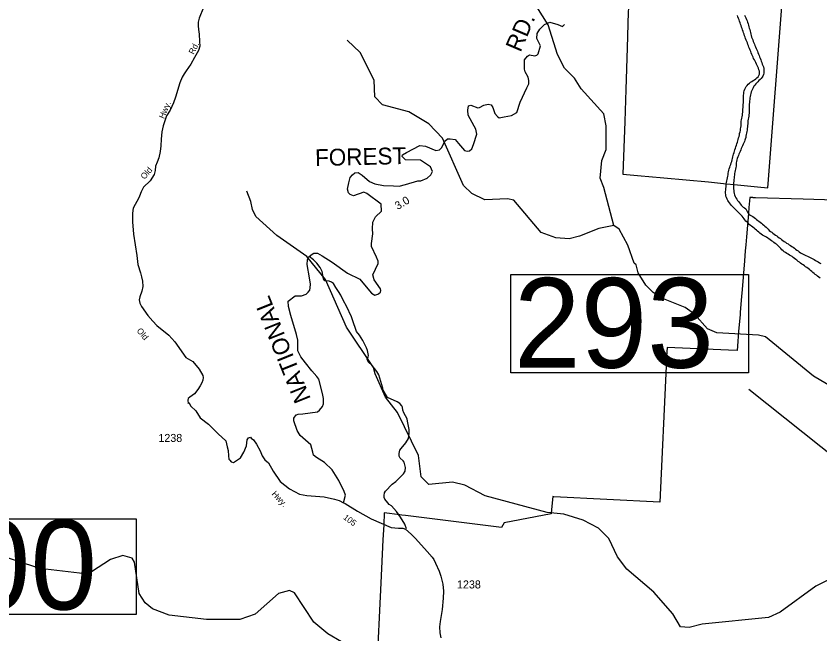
# Model space of a CAD drawing. Extents: x 1113032 to 1302912, y 664689 to 832535.
# Drawn here: x 1126972 to 1139525, y 756257 to 765901 of the extents above; entities that cross this region are included whole.
import ezdxf

# ---------------------------------------------------------------- set-up
doc = ezdxf.new("R2010")
doc.units = 0
for name, color, linetype in [('Exist Boundary Land Use Forest National US Forest Service', 7, 'Continuous'), ('Exist Hydrographic Creek Single Shore', 7, 'Continuous'), ('Exist Hydrographic River Shore', 7, 'Continuous'), ('Exist Road Non-System Type 51', 7, 'Continuous'), ('Exist Road Primary NC Structure Pipe Number Label', 7, 'Continuous'), ('Exist Road Secondary Structure Standard Bridge Number Label', 7, 'Continuous'), ('Exist Road Secondary Type 41 Attributed', 7, 'Continuous'), ('Exist Road Secondary Type 51 Label', 7, 'Continuous'), ('Exist Road Secondary Type 51 Number Label', 7, 'Continuous'), ('Exist Road State Agency Type 20 National Forest', 7, 'Continuous'), ('Exist Road State Agency Type 41 Label', 7, 'Continuous'), ('Exist Road State Agency Type 41 Mileage Label', 7, 'Continuous')]:
    doc.layers.add(name, color=color, linetype=linetype)

msp = doc.modelspace()

# ---------------------------------------------------------------- linework, layer by layer
at = {"layer": 'Exist Boundary Land Use Forest National US Forest Service'}
for points in [[(1138713, 763223), (1138723, 763348), (1138943, 766193), (1138993, 766844), (1139021, 767208), (1138394, 767267), (1138077, 767670), (1137491, 768414), (1137470, 768440), (1137238, 768439), (1137082, 768438), (1137008, 768296), (1137011, 768288), (1136972, 768151), (1137018, 768103), (1137101, 768007), (1137113, 767991), (1137220, 767682), (1136825, 767454), (1136525, 767475), (1136621, 766751), (1136539, 766137)], [(1136539, 766137), (1136539, 766090), (1136530, 765960), (1136513, 765408), (1136497, 764754), (1136478, 764256), (1136446, 763434), (1136733, 763409), (1136853, 763399), (1137087, 763379), (1137787, 763312), (1138068, 763285), (1138186, 763274), (1138552, 763238), (1138713, 763223)], [(1138479, 763072), (1138432, 763072), (1138415, 762916), (1138408, 762820), (1138378, 762456), (1138368, 762329), (1138360, 762238), (1138347, 762083), (1138310, 761636), (1138301, 761526), (1138281, 761280), (1138278, 761242), (1138256, 760980), (1138237, 760749), (1138232, 760682), (1138099, 760687), (1137138, 760728), (1137132, 760594), (1137125, 760438), (1137024, 758315), (1135368, 758399), (1135352, 758400), (1135336, 758200), (1135331, 758131), (1134593, 757989), (1134555, 757920), (1133052, 758105), (1132995, 758112), (1132963, 758116), (1132722, 758146), (1132713, 757960), (1132702, 757727), (1132681, 757278), (1132670, 757055), (1132603, 755652)], [(1138479, 763072), (1138521, 763071), (1139266, 763048), (1140594, 763008), (1141070, 762998), (1142683, 762964), (1142926, 762959), (1142906, 762157), (1143300, 762142)]]:
    msp.add_lwpolyline(points, dxfattribs=at)
at = {"layer": 'Exist Hydrographic Creek Single Shore'}
for points in [[(1136308, 762631), (1136150, 763228), (1136096, 763371), (1136121, 763646), (1136185, 763818), (1136187, 764186), (1136151, 764377), (1135796, 764765), (1135692, 764934), (1135538, 765088), (1135428, 765301), (1135283, 765763), (1135044, 766145), (1134305, 766800)], [(1136308, 762631), (1136073, 762586), (1135769, 762465), (1135610, 762425), (1135402, 762442), (1135171, 762522), (1134744, 763027), (1134644, 763048), (1134294, 763032), (1134088, 763132), (1133958, 763259), (1133630, 763994), (1133420, 764218), (1133108, 764408), (1132695, 764515), (1132573, 764642), (1132564, 764902), (1132344, 765333), (1132141, 765524)], [(1139834, 757190), (1139461, 757001), (1138907, 756599), (1138721, 756514), (1137684, 756410), (1137483, 756358), (1137350, 756370), (1137230, 756573), (1136931, 756907), (1136508, 757270), (1136363, 757460), (1136231, 757745), (1136069, 757909), (1135830, 758032), (1135525, 758127), (1135266, 758152), (1134298, 758411), (1133978, 758581), (1133788, 758628), (1133420, 758589), (1133298, 758710), (1133258, 759042), (1132928, 759712), (1132743, 759952), (1132579, 760316), (1132556, 760415), (1132133, 761044), (1131805, 761789), (1131515, 762146), (1131042, 762477), (1130717, 762772), (1130662, 762882), (1130640, 763007), (1130578, 763166)], [(1139719, 760111), (1139424, 760278), (1138675, 760893), (1138567, 760922), (1137918, 760958), (1137770, 761020), (1137568, 761250), (1137421, 761355), (1137083, 761490), (1136919, 761588), (1136806, 761699), (1136686, 761895), (1136657, 762020), (1136624, 762047), (1136524, 762325), (1136390, 762577), (1136308, 762631)], [(1132055, 756135), (1131841, 756257), (1131622, 756439), (1131318, 756898), (1131244, 756936), (1131068, 756890), (1130708, 756566), (1130464, 756482), (1129947, 756482), (1129365, 756550), (1129101, 756647), (1128987, 756744), (1128892, 756887), (1128823, 757375), (1128783, 757441), (1128642, 757480), (1128449, 757418), (1128151, 757227), (1128050, 757196), (1127344, 757276), (1126625, 757514)]]:
    msp.add_lwpolyline(points, dxfattribs=at)
at = {"layer": 'Exist Hydrographic River Shore'}
for points in [[(1138502, 765217), (1138490, 765238), (1138481, 765260), (1138472, 765282), (1138463, 765304), (1138454, 765327), (1138445, 765349), (1138436, 765371), (1138426, 765393), (1138417, 765415), (1138408, 765437), (1138399, 765460), (1138392, 765482), (1138383, 765505), (1138373, 765527), (1138364, 765549), (1138356, 765571), (1138348, 765594), (1138340, 765617), (1138332, 765639), (1138325, 765662), (1138317, 765685), (1138310, 765708), (1138302, 765731), (1138294, 765753), (1138286, 765776), (1138278, 765798), (1138270, 765821), (1138262, 765844), (1138253, 765866), (1138246, 765889), (1138240, 765912)], [(1138349, 765916), (1138359, 765894), (1138369, 765872), (1138378, 765850), (1138387, 765828), (1138395, 765805), (1138403, 765782), (1138410, 765759), (1138416, 765736), (1138423, 765713), (1138431, 765691), (1138437, 765667), (1138440, 765644), (1138444, 765620), (1138450, 765597), (1138458, 765574), (1138466, 765551), (1138476, 765529), (1138485, 765507)], [(1138485, 765507), (1138493, 765485), (1138502, 765462), (1138511, 765440), (1138519, 765419), (1138530, 765398), (1138540, 765376), (1138550, 765354), (1138558, 765332), (1138566, 765309), (1138575, 765287), (1138583, 765264), (1138592, 765242), (1138601, 765220), (1138609, 765197), (1138618, 765175), (1138626, 765152), (1138635, 765130), (1138643, 765107), (1138648, 765084), (1138650, 765060), (1138652, 765036), (1138650, 765012), (1138644, 764989), (1138635, 764966), (1138622, 764946), (1138607, 764928), (1138590, 764911), (1138572, 764894), (1138555, 764877), (1138539, 764859), (1138523, 764842), (1138507, 764824), (1138491, 764806), (1138481, 764784), (1138471, 764762), (1138460, 764741), (1138454, 764718), (1138448, 764695), (1138443, 764671), (1138437, 764648), (1138433, 764624), (1138429, 764600), (1138426, 764577), (1138424, 764553), (1138422, 764529), (1138421, 764505), (1138422, 764481), (1138422, 764457), (1138422, 764433), (1138423, 764409), (1138421, 764385), (1138417, 764361), (1138413, 764338), (1138409, 764314), (1138405, 764290), (1138402, 764266), (1138399, 764243), (1138398, 764219), (1138395, 764195), (1138393, 764171), (1138391, 764147), (1138388, 764123), (1138384, 764100), (1138380, 764076), (1138376, 764052), (1138371, 764029), (1138366, 764005), (1138359, 763982), (1138354, 763964), (1138347, 763944), (1138338, 763922), (1138328, 763900), (1138318, 763878), (1138307, 763857), (1138298, 763835), (1138289, 763812), (1138280, 763790), (1138271, 763768), (1138261, 763746), (1138252, 763724), (1138243, 763702), (1138235, 763679), (1138229, 763656), (1138224, 763632), (1138220, 763609), (1138217, 763585), (1138215, 763561), (1138212, 763537), (1138207, 763514), (1138201, 763490), (1138196, 763467), (1138192, 763443), (1138190, 763419), (1138188, 763395), (1138184, 763372), (1138182, 763348), (1138180, 763324), (1138178, 763300), (1138176, 763276)], [(1138100, 763005), (1138087, 763025), (1138075, 763046), (1138065, 763068), (1138058, 763091), (1138054, 763115), (1138053, 763138), (1138053, 763162), (1138054, 763186), (1138056, 763210), (1138059, 763234), (1138061, 763258), (1138063, 763282), (1138066, 763306), (1138072, 763329), (1138079, 763352), (1138084, 763375), (1138088, 763400), (1138091, 763424), (1138093, 763448), (1138097, 763472), (1138102, 763495), (1138108, 763518), (1138117, 763541), (1138126, 763563), (1138133, 763586), (1138140, 763609), (1138148, 763632), (1138153, 763655), (1138158, 763679), (1138163, 763702), (1138170, 763725), (1138177, 763748), (1138185, 763771), (1138192, 763793), (1138199, 763816), (1138207, 763839), (1138214, 763862), (1138222, 763885), (1138229, 763908), (1138236, 763931), (1138243, 763954), (1138250, 763977), (1138256, 764000), (1138263, 764023), (1138268, 764046), (1138272, 764070), (1138278, 764093), (1138283, 764117), (1138287, 764140), (1138290, 764164), (1138294, 764188), (1138294, 764212), (1138293, 764236), (1138295, 764260), (1138300, 764283), (1138305, 764307), (1138310, 764330), (1138314, 764354), (1138317, 764378), (1138319, 764401), (1138322, 764425), (1138324, 764449), (1138327, 764473), (1138329, 764497), (1138329, 764521), (1138330, 764545), (1138330, 764569), (1138330, 764593), (1138331, 764617), (1138332, 764641), (1138334, 764665), (1138336, 764689), (1138339, 764713), (1138344, 764736), (1138351, 764759), (1138362, 764780), (1138376, 764800), (1138391, 764819), (1138407, 764837), (1138424, 764854), (1138443, 764868), (1138463, 764882), (1138483, 764895), (1138503, 764908), (1138523, 764922), (1138542, 764936), (1138560, 764953), (1138574, 764972), (1138583, 764994), (1138584, 765018), (1138580, 765042), (1138574, 765065), (1138565, 765087), (1138554, 765109), (1138545, 765131), (1138536, 765153), (1138525, 765175), (1138514, 765196), (1138502, 765217)], [(1138176, 763276), (1138175, 763252), (1138177, 763228), (1138178, 763204), (1138180, 763180)], [(1138180, 763180), (1138183, 763156), (1138187, 763132), (1138194, 763110), (1138203, 763087), (1138214, 763066), (1138226, 763045), (1138239, 763025), (1138254, 763006), (1138268, 762987), (1138283, 762968), (1138298, 762949), (1138311, 762936), (1138327, 762918), (1138349, 762907), (1138369, 762894), (1138381, 762873), (1138389, 762851), (1138401, 762830), (1138415, 762811), (1138436, 762793), (1138456, 762781), (1138477, 762771), (1138498, 762758), (1138518, 762744), (1138535, 762728), (1138554, 762712), (1138573, 762698), (1138592, 762684), (1138611, 762670), (1138631, 762655), (1138650, 762640), (1138667, 762624), (1138684, 762607), (1138700, 762590), (1138717, 762573), (1138735, 762557), (1138754, 762541), (1138772, 762526), (1138791, 762511), (1138810, 762497), (1138830, 762483), (1138850, 762470), (1138870, 762456), (1138889, 762442), (1138908, 762427), (1138927, 762412), (1138946, 762398), (1138966, 762384), (1138986, 762371), (1139006, 762359), (1139027, 762346), (1139047, 762333), (1139067, 762319), (1139086, 762306), (1139106, 762292), (1139126, 762278), (1139145, 762264), (1139164, 762250), (1139184, 762236), (1139203, 762222), (1139223, 762208), (1139244, 762195), (1139264, 762183), (1139285, 762172), (1139307, 762162), (1139329, 762153), (1139352, 762143), (1139373, 762133), (1139395, 762122), (1139416, 762111), (1139437, 762100), (1139458, 762088), (1139479, 762076), (1139499, 762063), (1139520, 762050), (1139540, 762037)], [(1139528, 761810), (1139509, 761825), (1139490, 761840), (1139471, 761855), (1139452, 761870), (1139433, 761885), (1139415, 761900), (1139397, 761916), (1139379, 761932), (1139361, 761948), (1139342, 761962), (1139322, 761975), (1139302, 761989), (1139282, 762002), (1139263, 762016), (1139243, 762030), (1139223, 762044), (1139204, 762058), (1139186, 762073), (1139167, 762089), (1139149, 762104), (1139130, 762119), (1139110, 762133), (1139090, 762147), (1139070, 762159), (1139049, 762171), (1139029, 762183), (1139008, 762196), (1138988, 762210), (1138969, 762224), (1138950, 762239), (1138932, 762255), (1138916, 762272), (1138899, 762290), (1138883, 762307), (1138865, 762323), (1138847, 762339), (1138828, 762353), (1138808, 762367), (1138789, 762381), (1138769, 762395), (1138749, 762409), (1138730, 762423), (1138710, 762436), (1138689, 762449), (1138668, 762460), (1138647, 762472), (1138627, 762484), (1138607, 762497), (1138587, 762511), (1138569, 762526), (1138551, 762542), (1138533, 762559), (1138515, 762574), (1138496, 762590), (1138478, 762605), (1138459, 762620), (1138440, 762635), (1138422, 762650), (1138404, 762667), (1138387, 762684), (1138371, 762701), (1138355, 762719), (1138340, 762738), (1138325, 762757), (1138311, 762776), (1138295, 762794), (1138278, 762811), (1138261, 762828), (1138244, 762845), (1138227, 762862), (1138210, 762879), (1138193, 762896), (1138175, 762912), (1138158, 762929), (1138142, 762947), (1138127, 762965), (1138113, 762985), (1138100, 763005)]]:
    msp.add_lwpolyline(points, dxfattribs=at)
at = {"layer": 'Exist Road Non-System Type 51'}
msp.add_lwpolyline([(1133070, 757896), (1133041, 757970), (1132976, 758082), (1132911, 758168), (1132835, 758254), (1132800, 758279), (1132776, 758304), (1132730, 758363), (1132721, 758389), (1132723, 758397), (1132720, 758419), (1132725, 758459), (1132742, 758485), (1132847, 758594), (1132905, 758638), (1132985, 758718), (1133022, 758757), (1133047, 758798), (1133053, 758856), (1133031, 758940), (1133018, 758961), (1132971, 759000), (1132954, 759031), (1132953, 759071), (1132965, 759123), (1132986, 759152), (1133060, 759240), (1133100, 759309), (1133109, 759387), (1133112, 759447), (1133083, 759580), (1133079, 759616), (1133026, 759709), (1133013, 759750), (1133005, 759796), (1132995, 759820), (1132964, 759855), (1132923, 759882), (1132771, 759945), (1132707, 760063), (1132701, 760095), (1132639, 760303), (1132607, 760356), (1132534, 760446), (1132469, 760502), (1132455, 760547), (1132470, 760582), (1132476, 760604), (1132461, 760679), (1132442, 760725), (1132387, 760835), (1132333, 760921), (1132289, 760980), (1132225, 761162), (1132212, 761206), (1132133, 761375), (1132083, 761454), (1132042, 761545), (1132007, 761603), (1131965, 761664), (1131931, 761727), (1131896, 761748), (1131860, 761763), (1131792, 761769), (1131771, 761798), (1131752, 761912), (1131722, 761977), (1131670, 762047), (1131616, 762099), (1131550, 762148)], dxfattribs=at)
at = {"layer": 'Exist Road Primary NC Structure Pipe Number Label'}
msp.add_lwpolyline([(1123852, 758051), (1128850, 758051), (1128850, 756559), (1123852, 756559)], close=True, dxfattribs=at)
at = {"layer": 'Exist Road Secondary Structure Standard Bridge Number Label'}
msp.add_line((1141184, 757866), (1138414, 760075), dxfattribs=at)
msp.add_lwpolyline([(1134696, 761870), (1138412, 761870), (1138412, 760333), (1134696, 760333)], close=True, dxfattribs=at)
at = {"layer": 'Exist Road Secondary Type 41 Attributed'}
for points in [[(1129900, 766035), (1129833, 765870), (1129817, 765805), (1129817, 765748), (1129823, 765691), (1129830, 765620), (1129837, 765507), (1129842, 765434), (1129822, 765362), (1129760, 765255), (1129700, 765153), (1129628, 765048)], [(1129628, 765048), (1129595, 765002), (1129566, 764947), (1129529, 764859), (1129461, 764636), (1129431, 764549), (1129378, 764433), (1129320, 764345), (1129268, 764189), (1129247, 764095), (1129238, 763982), (1129235, 763877), (1129223, 763788), (1129201, 763687), (1129173, 763623), (1129150, 763557), (1129146, 763493), (1129127, 763429), (1129065, 763332), (1128963, 763230), (1128924, 763159), (1128899, 763090), (1128882, 763056), (1128831, 762962), (1128802, 762904), (1128788, 762826), (1128791, 762689), (1128806, 762499), (1128857, 762163), (1128873, 762022), (1128914, 761896), (1128933, 761830), (1128946, 761763), (1128953, 761681), (1128938, 761608), (1128906, 761521), (1128895, 761473), (1128904, 761418), (1128932, 761370), (1129032, 761228), (1129108, 761139), (1129171, 761073), (1129358, 760918), (1129453, 760814), (1129624, 760571), (1129735, 760510), (1129831, 760392), (1129889, 760290), (1129896, 760261), (1129888, 760219), (1129873, 760175), (1129849, 760128), (1129812, 760070), (1129756, 760004), (1129688, 759952), (1129662, 759934), (1129654, 759907), (1129662, 759853), (1129669, 759869), (1129701, 759810), (1129778, 759737), (1129849, 759629), (1129977, 759529), (1130126, 759382), (1130250, 759270), (1130271, 759180), (1130283, 759119), (1130287, 759039), (1130293, 758986), (1130309, 758969), (1130330, 758941), (1130369, 758932), (1130479, 759004), (1130529, 759092), (1130571, 759194), (1130581, 759286), (1130604, 759319), (1130631, 759330), (1130646, 759313), (1130682, 759286), (1130726, 759218), (1130784, 759113), (1130815, 759036), (1130858, 758975), (1130916, 758927), (1130989, 758800), (1131098, 758635), (1131243, 758524), (1131396, 758437), (1131514, 758419), (1131781, 758395), (1131946, 758362), (1132017, 758339), (1132087, 758304)], [(1132087, 758304), (1132111, 758292), (1132304, 758175), (1132517, 758056), (1132831, 757916), (1132946, 757906), (1133013, 757906), (1133055, 757890), (1133141, 757814), (1133209, 757747), (1133394, 757545), (1133472, 757454), (1133498, 757418), (1133524, 757361), (1133578, 757236), (1133603, 757160), (1133635, 757033), (1133647, 756924), (1133643, 756815), (1133625, 756636), (1133594, 756452), (1133584, 756370), (1133591, 756272), (1133603, 756195)]]:
    msp.add_lwpolyline(points, dxfattribs=at)
at = {"layer": 'Exist Road State Agency Type 20 National Forest'}
for points in [[(1132866, 763251), (1132954, 763246), (1133055, 763271), (1133247, 763329), (1133293, 763328), (1133391, 763372), (1133451, 763423), (1133476, 763477), (1133443, 763549), (1133290, 763653), (1133055, 763658), (1133000, 763712), (1133008, 763735), (1133068, 763774), (1133275, 763880), (1133365, 763873), (1133526, 763805), (1133582, 763816), (1133618, 763843), (1133638, 763880), (1133670, 763950), (1133708, 763986), (1133752, 763986), (1133827, 763975), (1133879, 763913), (1133975, 763802), (1134019, 763792), (1134055, 763797), (1134089, 763831), (1134117, 763895), (1134169, 764056), (1134153, 764136), (1134127, 764185), (1134034, 764353), (1134026, 764434), (1134039, 764501), (1134076, 764511), (1134184, 764470), (1134210, 764472), (1134277, 764511), (1134345, 764529), (1134391, 764514), (1134420, 764475), (1134451, 764379), (1134492, 764333), (1134518, 764312), (1134595, 764330), (1134707, 764351), (1134792, 764396), (1134846, 764559), (1134949, 764779), (1134980, 764843), (1134980, 764895), (1134970, 764949), (1134923, 765032), (1134913, 765074), (1134911, 765219), (1134960, 765278), (1134988, 765296), (1135071, 765283), (1135102, 765291), (1135127, 765312), (1135160, 765435), (1135102, 765554), (1135110, 765628), (1135151, 765698), (1135225, 765772), (1135307, 765805), (1135430, 765768), (1135504, 765739), (1135537, 765768)], [(1132087, 758304), (1132119, 758421), (1132095, 758482), (1132010, 758654), (1131908, 758819), (1131789, 758931), (1131665, 759010), (1131619, 759048), (1131604, 759094), (1131573, 759209), (1131409, 759354), (1131364, 759435), (1131308, 759582), (1131311, 759625), (1131344, 759679), (1131349, 759678), (1131380, 759687), (1131452, 759695), (1131680, 759726), (1131712, 759751), (1131759, 759809), (1131771, 759848), (1131774, 759932), (1131756, 760009), (1131698, 760234), (1131669, 760275), (1131589, 760366), (1131492, 760488), (1131419, 760580), (1131373, 760674), (1131372, 760843), (1131352, 760933), (1131261, 761227), (1131226, 761370), (1131223, 761450), (1131330, 761536), (1131432, 761533), (1131504, 761563), (1131535, 761591), (1131561, 761621), (1131567, 761662), (1131569, 761718), (1131555, 761816), (1131518, 762026), (1131521, 762096), (1131540, 762138), (1131578, 762175), (1131620, 762198), (1131678, 762199), (1131754, 762158), (1131909, 762059), (1132148, 761889), (1132338, 761796), (1132414, 761704), (1132522, 761575), (1132575, 761546), (1132623, 761560), (1132638, 761573), (1132662, 761594), (1132666, 761617), (1132665, 761645), (1132564, 761786), (1132546, 761863), (1132628, 762037), (1132625, 762077), (1132601, 762139), (1132524, 762306), (1132521, 762352), (1132546, 762502), (1132536, 762579), (1132543, 762683), (1132585, 762769), (1132677, 762857), (1132674, 762963), (1132452, 763131), (1132403, 763152), (1132243, 763095), (1132191, 763114), (1132166, 763144), (1132150, 763202), (1132169, 763299), (1132192, 763380), (1132226, 763424), (1132265, 763454), (1132315, 763458), (1132375, 763420), (1132491, 763320), (1132576, 763281), (1132712, 763258), (1132866, 763251)]]:
    msp.add_lwpolyline(points, dxfattribs=at)

# ---------------------------------------------------------------- texts
at = {"layer": 'Exist Road Primary NC Structure Pipe Number Label'}
msp.add_text('P300', height=1400, dxfattribs=at).set_placement((1123865, 756638))
at = {"layer": 'Exist Road Secondary Structure Standard Bridge Number Label'}
msp.add_text('293', height=1400, dxfattribs=at).set_placement((1134746, 760412))
at = {"layer": 'Exist Road Secondary Type 51 Label'}
for s, rotation, p in [('Rd.', 63.1276, (1129746, 765294)), ('Hwy.', 67.0537, (1129284, 764290)), ('Old', 48.9936, (1128978, 763344)), ('Old', 309.6797, (1128849, 760986)), ('Hwy.', 313.7276, (1130957, 758435)), ('105', 323.3993, (1132073, 758059))]:
    msp.add_text(s, height=95, rotation=rotation, dxfattribs=at).set_placement(p)
at = {"layer": 'Exist Road Secondary Type 51 Number Label'}
for p in [(1129195, 759254), (1133858, 756967)]:
    msp.add_text('1238', height=125, dxfattribs=at).set_placement(p)
at = {"layer": 'Exist Road State Agency Type 41 Label'}
for s, rotation, p in [('RD.', 66.927, (1134849, 765325)), ('FOREST', 1.3088, (1131644, 763560)), ('NATIONAL', 111.927, (1131578, 759926))]:
    msp.add_text(s, height=262.5, rotation=rotation, dxfattribs=at).set_placement(p)
at = {"layer": 'Exist Road State Agency Type 41 Mileage Label'}
msp.add_text('3.0', height=125, rotation=30.7436, dxfattribs=at).set_placement((1132932, 762873))

doc.saveas('drawing.dxf')
